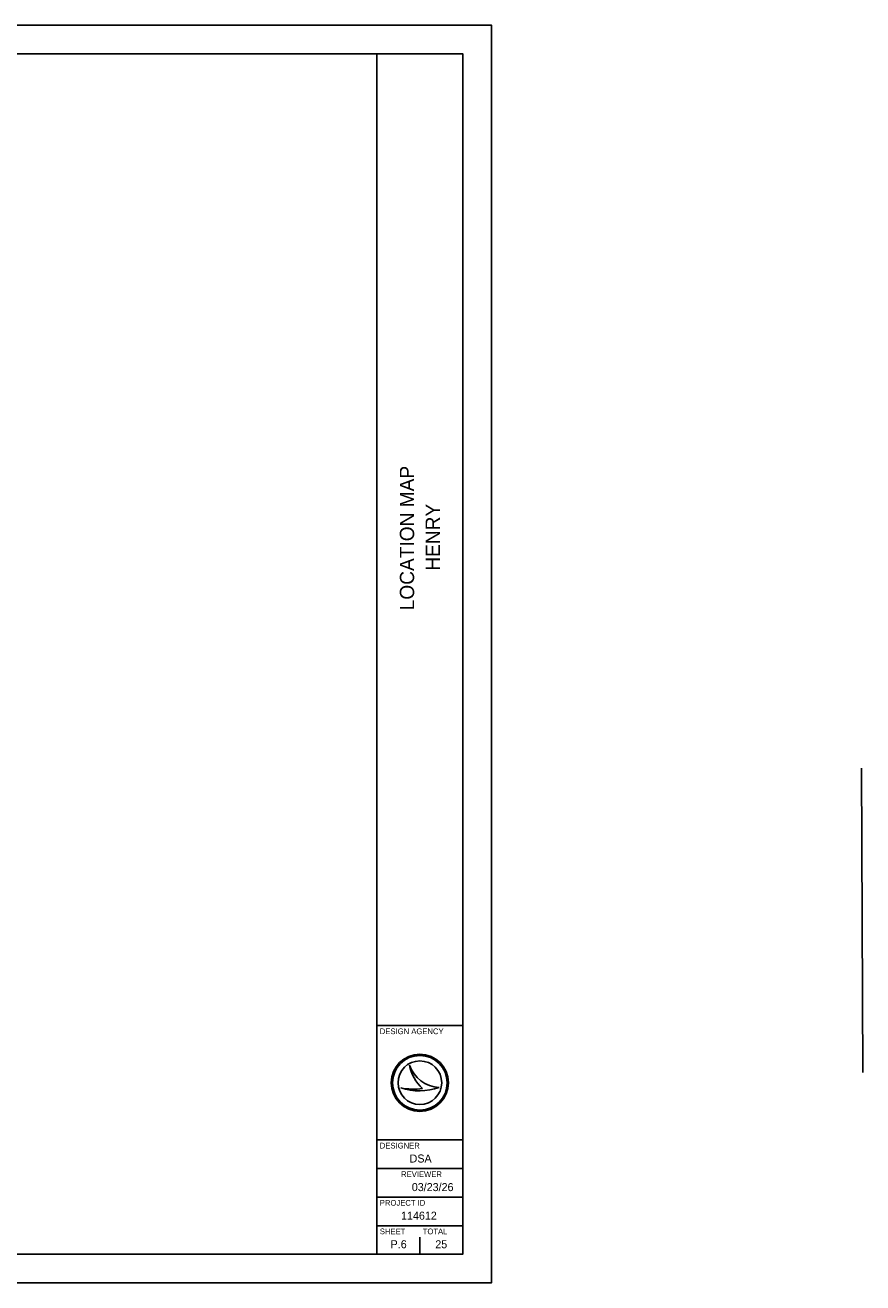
# Model space of a CAD drawing. Extents: x -62 to 810, y 0 to 440.
# Drawn here: x 517 to 809.9, y 0 to 440 of the extents above; entities that cross this region are included whole.
import ezdxf

# ---------------------------------------------------------------- set-up
doc = ezdxf.new("R2010")
doc.units = 0
for name, color, linetype in [('RD_P_Fence', 7, 'Continuous'), ('SH_Border', 7, 'Continuous'), ('SH_Cut_Line', 7, 'Continuous'), ('SH_Data', 7, 'Continuous')]:
    doc.layers.add(name, color=color, linetype=linetype)

msp = doc.modelspace()

# ---------------------------------------------------------------- linework, layer by layer
at = {"layer": 'RD_P_Fence'}
msp.add_line((809.86, 73.61), (809.37, 180.04), dxfattribs=at)
at = {"layer": 'SH_Border'}
for p, q in [((640, 10), (640, 430)), ((640, 90), (670, 90)), ((640, 50), (670, 50)), ((640, 40), (670, 40)), ((640, 30), (670, 30)), ((640, 20), (670, 20))]:
    msp.add_line(p, q, dxfattribs=at)
msp.add_lwpolyline([(30, 430), (670, 430), (670, 10), (30, 10)], close=True, dxfattribs=at)
at = {"layer": 'SH_Cut_Line'}
msp.add_lwpolyline([(0, 0), (680, 0), (680, 440), (0, 440)], close=True, dxfattribs=at)
at = {"layer": 'SH_Data'}
for p, q in [((651.35, 76.19), (651.35, 76.19)), ((648.34, 68.19), (648.34, 68.19)), ((655, 70), (655, 70)), ((661.75, 68.37), (661.75, 68.37)), ((647.5, 13.5), (647.5, 13.5)), ((655, 10), (655, 16))]:
    msp.add_line(p, q, dxfattribs=at)
for radius in [10, 9.54, 9.54, 7.64]:
    msp.add_circle((655, 70), radius, dxfattribs=at)
for centre, radius, start, end in [((662.32, 79.95), 11.6, 198.9257, 198.9319), ((666.93, 79.4), 15.91, 191.6379, 191.6421), ((662.32, 79.95), 11.6, 198.9319, 267.1657), ((666.93, 79.4), 15.91, 191.6421, 226.0947), ((654.79, 87.4), 20.26, 251.4576, 290.0832), ((652.96, 93.09), 25.32, 259.4964, 259.4995), ((654.79, 87.4), 20.26, 251.4527, 251.4576), ((652.96, 93.09), 25.32, 259.4995, 276.6672)]:
    msp.add_arc(centre, radius, start, end, dxfattribs=at)

# ---------------------------------------------------------------- texts
for s, p in [('LOCATION MAP', (653, 235.29)), ('HENRY', (662, 249.14))]:
    msp.add_text(s, height=5, rotation=90, dxfattribs=at).set_placement(p)
for s, height, p in [('DESIGN AGENCY', 2, (641, 87)), ('DESIGNER', 2, (641, 47)), ('DSA', 2.8, (651.41, 42.1)), ('REVIEWER', 2, (648.44, 37)), ('03/23/26', 2.8, (652.18, 32.1)), ('PROJECT ID', 2, (641, 27)), ('114612', 2.8, (648.42, 22.1)), ('SHEET', 2, (641, 17)), ('TOTAL', 2, (656, 17)), ('P.6', 2.8, (644.77, 12.1)), ('25', 2.8, (660.39, 12.1))]:
    msp.add_text(s, height=height, dxfattribs=at).set_placement(p)

doc.saveas('drawing.dxf')
